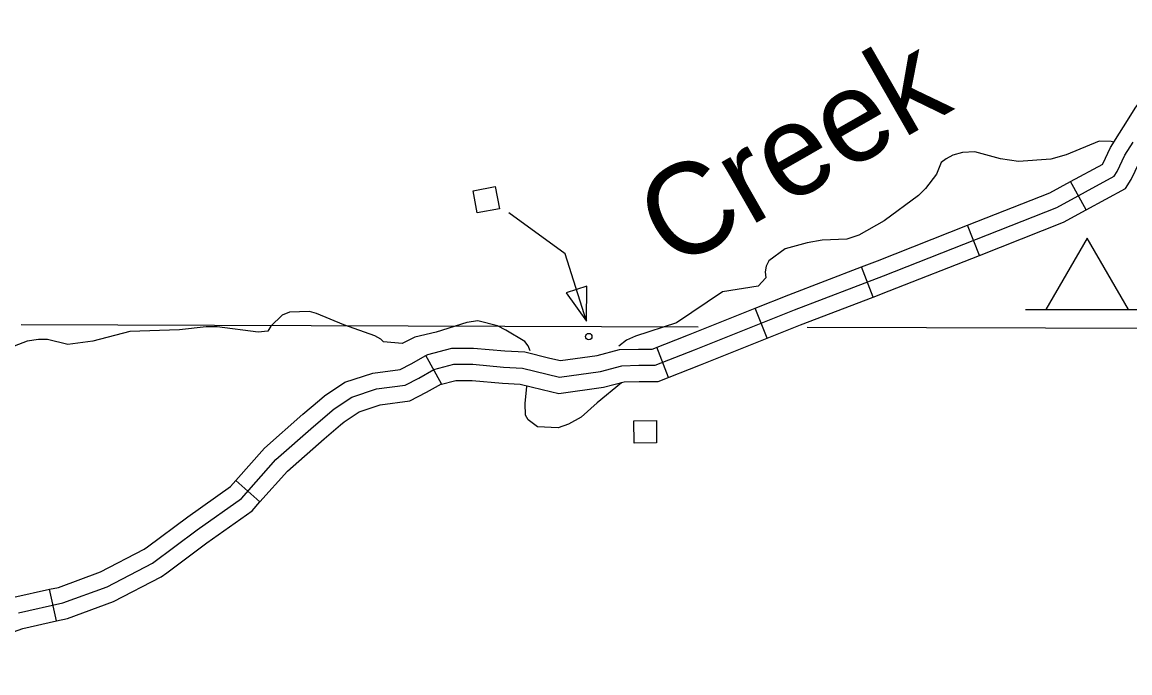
# Model space of a CAD drawing. Extents: x -19 to 366, y -4 to 359.
# Drawn here: x 136.395 to 137.366, y 192.721 to 193.292 of the extents above; entities that cross this region are included whole.
import ezdxf

# ---------------------------------------------------------------- set-up
doc = ezdxf.new("R2010")
doc.units = 0
for name, color, linetype in [('Level 32', 7, 'Continuous'), ('Level 35', 7, 'Continuous'), ('Level 45', 7, 'Continuous'), ('Level 5', 7, 'Continuous'), ('Level 56', 7, 'Continuous'), ('Level 57', 7, 'Continuous'), ('Level 60', 7, 'Continuous')]:
    doc.layers.add(name, color=color, linetype=linetype)

msp = doc.modelspace()

# ---------------------------------------------------------------- linework, layer by layer
at = {"layer": 'Level 32'}
for p, q in [((137.32783, 193.12685), (137.31425, 193.15181)), ((137.23433, 193.08706), (137.22392, 193.11349)), ((137.14111, 193.05048), (137.13096, 193.07702)), ((137.04809, 193.01438), (137.03753, 193.04075)), ((136.96162, 192.98003), (136.95127, 193.00648))]:
    msp.add_line(p, q, dxfattribs=at)
for points in [[(137.31425, 193.15181), (137.34247, 193.16716), (137.34263, 193.16741), (137.34935, 193.18177), (137.35714, 193.19412), (137.36434, 193.20534), (137.37102, 193.21627), (137.37321, 193.21955)], [(137.32783, 193.12685), (137.36242, 193.14567), (137.36756, 193.15364), (137.37433, 193.16812), (137.3811, 193.17886), (137.38842, 193.19026), (137.39497, 193.20098), (137.39685, 193.2038)], [(137.35245, 193.15641), (137.35509, 193.16053), (137.36184, 193.17495), (137.36912, 193.18649)], [(136.94986, 192.99068), (136.98444, 193.00421), (137.0722, 193.03933), (137.15015, 193.06915), (137.30211, 193.12904), (137.35245, 193.15641)], [(137.22391, 193.11349), (137.29609, 193.14193), (137.31425, 193.15181)], [(137.23433, 193.08706), (137.30813, 193.11614), (137.32783, 193.12685)], [(137.13096, 193.07702), (137.14501, 193.08239), (137.22391, 193.11349)], [(137.14111, 193.05048), (137.15529, 193.05591), (137.23433, 193.08706)], [(137.03753, 193.04075), (137.06702, 193.05255), (137.13096, 193.07702)], [(137.04809, 193.01438), (137.07738, 193.0261), (137.14111, 193.05048)], [(136.94718, 193.00488), (136.97921, 193.01742), (137.03753, 193.04075)], [(136.95255, 192.97647), (136.98967, 192.991), (137.04809, 193.01438)]]:
    msp.add_lwpolyline(points, dxfattribs=at)
at = {"layer": 'Level 35'}
for points in [[(137.35224, 193.1865), (137.34982, 193.18682), (137.33923, 193.18716), (137.31054, 193.17529), (137.29694, 193.17145), (137.26859, 193.16944), (137.2527, 193.17166), (137.23037, 193.17802), (137.21941, 193.17722), (137.2111, 193.17491), (137.20506, 193.17186), (137.20091, 193.16843), (137.1968, 193.15817), (137.18702, 193.14561), (137.181, 193.13952), (137.15084, 193.1174), (137.12858, 193.10479), (137.11801, 193.10134), (137.09646, 193.1005), (137.08324, 193.09817), (137.06398, 193.09279), (137.04965, 193.08211), (137.0474, 193.07755), (137.04629, 193.07261), (137.04707, 193.06731), (137.04029, 193.06007), (137.00893, 193.05502), (136.96859, 193.02793), (136.93272, 193.01603), (136.92479, 193.01259), (136.91813, 193.00742)], [(136.84014, 193.00331), (136.83865, 193.0076), (136.83569, 193.01156), (136.81901, 193.02131), (136.8115, 193.0253), (136.79447, 193.02971), (136.78473, 193.0282), (136.7577, 193.01966), (136.73909, 193.01519), (136.72813, 193.00979), (136.71171, 193.0112), (136.70924, 193.01367), (136.70411, 193.01632), (136.67682, 193.02603), (136.65292, 193.03599), (136.64671, 193.0378), (136.62931, 193.03723)], [(136.62931, 193.03723), (136.62289, 193.03455), (136.61272, 193.02502), (136.6101, 193.02046), (136.60178, 193.01967), (136.56584, 193.02447), (136.55601, 193.02443), (136.53258, 193.02168), (136.4891, 193.02038), (136.45662, 193.01191), (136.4347, 193.00879), (136.41691, 193.01328), (136.40897, 193.01325), (136.39914, 193.01169), (136.38782, 193.00747)], [(136.83848, 192.94275), (136.83619, 192.94691), (136.83577, 192.95715), (136.83722, 192.97196), (136.83706, 192.97256)], [(136.92026, 192.9751), (136.89891, 192.95777), (136.88498, 192.9452), (136.87404, 192.93909), (136.86498, 192.93564), (136.84682, 192.93671), (136.83848, 192.94275)]]:
    msp.add_lwpolyline(points, dxfattribs=at)
at = {"layer": 'Level 45'}
for p, q in [((136.7626, 192.97441), (136.74867, 192.99917)), ((136.60332, 192.87072), (136.5821, 192.8896)), ((136.42495, 192.76631), (136.41876, 192.79404))]:
    msp.add_line(p, q, dxfattribs=at)
for points in [[(136.65562, 192.96009), (136.65993, 192.96372), (136.67759, 192.97566), (136.70236, 192.98376), (136.72617, 192.98694), (136.73581, 192.99193), (136.74867, 192.99917)], [(136.74866, 192.99916), (136.7505, 193.0002), (136.77152, 193.00571), (136.79065, 193.00571), (136.81804, 193.00318), (136.83573, 193.00229), (136.85763, 192.99695)], [(136.85763, 192.99695), (136.86685, 192.99471), (136.89908, 192.99921), (136.91857, 193.00441), (136.93541, 193.00487), (136.94718, 193.00488)], [(136.39142, 192.77337), (136.43053, 192.78212), (136.46922, 192.79627), (136.50916, 192.81708), (136.54827, 192.84622), (136.58696, 192.8737), (136.61733, 192.90783), (136.6502, 192.93697), (136.66851, 192.95237), (136.6839, 192.96278), (136.70553, 192.96986), (136.7305, 192.97319), (136.74256, 192.97943), (136.75588, 192.98692), (136.77335, 192.9915), (136.78999, 192.9915), (136.81703, 192.98901), (136.83368, 192.98817), (136.86613, 192.98026), (136.90191, 192.98526), (136.92063, 192.99025), (136.93561, 192.99067), (136.94986, 192.99068)], [(136.67391, 192.93836), (136.67708, 192.94102), (136.69021, 192.9499), (136.70871, 192.95595), (136.73483, 192.95943), (136.74931, 192.96693), (136.7626, 192.97441)], [(136.76125, 192.97365), (136.77518, 192.9773), (136.78934, 192.9773), (136.81603, 192.97483), (136.83162, 192.97405), (136.8509, 192.96935)], [(136.8509, 192.96935), (136.8654, 192.96582), (136.90473, 192.97131), (136.92269, 192.9761), (136.93581, 192.97647), (136.95255, 192.97647)], [(136.5821, 192.8896), (136.60728, 192.9179), (136.64091, 192.94772), (136.65562, 192.96009)], [(136.60332, 192.87072), (136.62739, 192.89776), (136.65949, 192.92622), (136.67391, 192.93836)], [(136.50458, 192.83139), (136.53991, 192.85771), (136.57742, 192.88434), (136.5821, 192.8896)], [(136.52156, 192.8086), (136.55663, 192.83474), (136.5965, 192.86305), (136.60332, 192.87072)], [(136.41876, 192.79404), (136.42652, 192.79578), (136.46347, 192.80929), (136.50159, 192.82915), (136.50458, 192.83139)], [(136.42495, 192.76631), (136.43454, 192.76846), (136.47497, 192.78325), (136.51674, 192.80501), (136.52156, 192.8086)], [(136.32418, 192.76892), (136.33083, 192.7696), (136.34389, 192.77105), (136.36152, 192.77795), (136.38751, 192.78706), (136.41876, 192.79404)], [(136.32708, 192.74066), (136.33385, 192.74135), (136.35075, 192.74323), (136.3714, 192.75131), (136.39533, 192.75969), (136.42495, 192.76631)]]:
    msp.add_lwpolyline(points, dxfattribs=at)
at = {"layer": 'Level 5'}
for points in [[(136.98752, 193.02417), (136.39393, 193.02618)], [(137.39691, 193.02279), (137.08328, 193.02385)]]:
    msp.add_lwpolyline(points, dxfattribs=at)
at = {"layer": 'Level 56'}
for points in [[(136.79383, 193.12435), (136.79019, 193.14373), (136.80963, 193.14738), (136.81327, 193.128)], [(136.89013, 193.05998), (136.87174, 193.05405), (136.88983, 193.02944)], [(136.95095, 192.94219), (136.95113, 192.92248), (136.93136, 192.92229), (136.93118, 192.942)]]:
    msp.add_lwpolyline(points, close=True, dxfattribs=at)
msp.add_lwpolyline([(136.88983, 193.02944), (136.87086, 193.08829), (136.82153, 193.12437)], dxfattribs=at)
msp.add_circle((136.89166, 193.01575), 0.00284, dxfattribs=at)
at = {"layer": 'Level 57'}
msp.add_line((137.2746, 193.03954), (137.38326, 193.03954), dxfattribs=at)
msp.add_lwpolyline([(137.29271, 193.03954), (137.36515, 193.03954), (137.32893, 193.10228)], close=True, dxfattribs=at)
at = {"layer": 'Level 60'}
for points in [[(139.44064, 1.53154), (139.25106, 10.14733), (139.06082, 18.76327), (138.86992, 27.37935), (138.67836, 35.99557), (138.48613, 44.61194), (138.29325, 53.22845), (138.09971, 61.84511), (137.9055, 70.46191), (137.71065, 79.07885), (137.51513, 87.69595), (137.31896, 96.31318), (137.12214, 104.93057), (136.92466, 113.54809), (136.72653, 122.16577), (136.52775, 130.78359), (136.32832, 139.40156), (136.12824, 148.01968), (135.9275, 156.63794), (135.72612, 165.25636), (135.5241, 173.87492), (135.32143, 182.49362), (135.11811, 191.11248), (134.91415, 199.73149), (134.70954, 208.35064), (134.50429, 216.96995), (134.2984, 225.5894), (134.09187, 234.209), (133.8847, 242.82876), (133.6769, 251.44866), (133.46845, 260.06872), (133.25937, 268.68892), (133.04965, 277.30928), (132.8393, 285.92978), (132.62831, 294.55044), (132.41669, 303.17125), (132.20444, 311.79221), (131.99156, 320.41333), (131.77805, 329.0346), (131.56391, 337.65601), (131.34914, 346.27759)], [(0, 189.51617), (7.11214, 189.52059), (14.22427, 189.53386), (21.33637, 189.55597), (28.44845, 189.58693), (35.56048, 189.62672), (42.67245, 189.67537), (49.78436, 189.73285), (56.89619, 189.79918), (64.00793, 189.87436), (71.11958, 189.95838), (78.23111, 190.05124), (85.34253, 190.15294), (92.45381, 190.26349), (99.56495, 190.38288), (106.67593, 190.51112), (113.78675, 190.6482), (120.89739, 190.79412), (128.00785, 190.94888), (135.11811, 191.11248), (142.22816, 191.28493), (149.33799, 191.46621), (156.44759, 191.65634), (163.55694, 191.85531), (170.66605, 192.06312), (177.77489, 192.27977), (184.88345, 192.50526), (191.99173, 192.73959), (199.09971, 192.98276), (206.20739, 193.23477), (213.31474, 193.49561), (220.42177, 193.7653), (227.52845, 194.04382), (234.63479, 194.33118), (241.74076, 194.62738), (248.84635, 194.93241), (255.95157, 195.24628), (263.05638, 195.56898), (270.16079, 195.90052), (277.26478, 196.24089), (284.36834, 196.5901), (291.47147, 196.94814), (298.57414, 197.31501), (305.67635, 197.69072), (312.77809, 198.07525), (319.87934, 198.46862), (326.9801, 198.87082), (334.08035, 199.28185), (341.18009, 199.7017)]]:
    msp.add_spline(points, degree=3, dxfattribs=at)

# ---------------------------------------------------------------- texts
at = {"layer": 'Level 35'}
msp.add_text('Creek', height=0.08, rotation=29.81359, dxfattribs=at).set_placement((136.96546, 193.07363))

doc.saveas('drawing.dxf')
